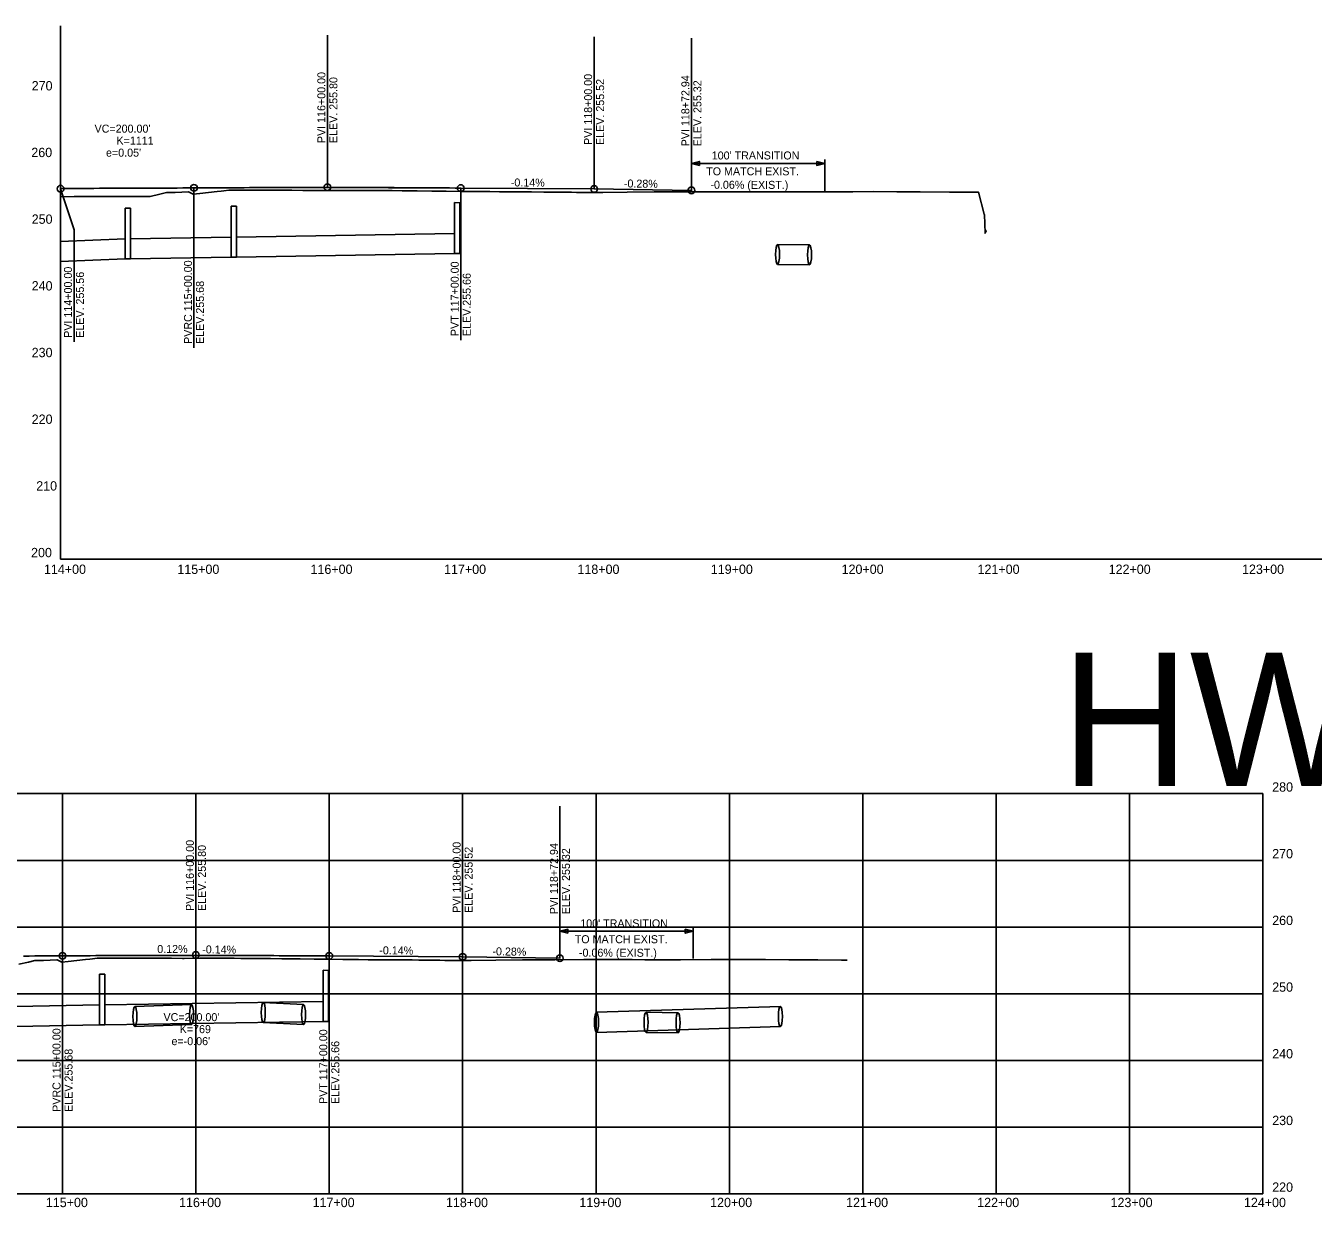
# Model space of a CAD drawing. Extents: x 1930770 to 1938778, y 596900 to 600561.
# Drawn here: x 1933865 to 1934830, y 598564 to 599450 of the extents above; entities that cross this region are included whole.
import ezdxf

# ---------------------------------------------------------------- set-up
doc = ezdxf.new("R2010")
doc.units = 0
for name, color, linetype in [('E_Tract Residual', 7, 'Continuous'), ('R_Concrete Hidden', 7, 'Continuous'), ('S_CROSS_DRAIN_ANNOT', 7, 'Continuous'), ('S_DROP_INLET_ANNOT', 7, 'Continuous'), ('S_ELECTRIC_UTILITIES_ANNOT', 7, 'Continuous'), ('S_HIST_HIGH_WATER_ANNOT', 7, 'Continuous'), ('S_SIGN_ANNOT', 7, 'Continuous'), ('S_STORM_SEWER_ANNOT', 7, 'Continuous'), ('S_UTILITY_POLE_ANNOT', 7, 'Continuous'), ('S_WATER_UTILITIES_ANNOT', 7, 'Continuous')]:
    doc.layers.add(name, color=color, linetype=linetype)

msp = doc.modelspace()

# ---------------------------------------------------------------- linework, layer by layer
at = {"layer": 'R_Concrete Hidden'}
for p, q in [((1933939.7, 599313.51), (1933943.7, 599313.66)), ((1933939.7, 599275.51), (1933939.7, 599313.51)), ((1933943.7, 599275.51), (1933943.7, 599313.66)), ((1934019.06, 599314.95), (1934023.06, 599315.06)), ((1934019.06, 599276.86), (1934019.06, 599314.95)), ((1934023.06, 599276.86), (1934023.06, 599315.06)), ((1934186.58, 599279.51), (1934186.58, 599317.88)), ((1934186.58, 599317.88), (1934190.58, 599317.6)), ((1934190.58, 599279.51), (1934190.58, 599317.6)), ((1934186.58, 599294.51), (1934023.06, 599291.86)), ((1933939.7, 599290.51), (1933891.24, 599288.55)), ((1934019.06, 599291.86), (1933943.7, 599290.51)), ((1934428.77, 599286.36), (1934452.75, 599286.06)), ((1933939.7, 599275.51), (1933891.24, 599273.55)), ((1933939.7, 599275.51), (1933943.7, 599275.51)), ((1934019.06, 599276.86), (1933943.7, 599275.51)), ((1934019.06, 599276.86), (1934023.06, 599276.86)), ((1934186.58, 599279.51), (1934023.06, 599276.86)), ((1934186.58, 599279.51), (1934190.58, 599279.51)), ((1934428.77, 599271.36), (1934452.75, 599271.06)), ((1933920.49, 598739.19), (1933924.49, 598739.3)), ((1933920.49, 598701.1), (1933920.49, 598739.19)), ((1933924.49, 598701.1), (1933924.49, 598739.3)), ((1934088.01, 598703.75), (1934088.01, 598742.13)), ((1934088.01, 598742.13), (1934092.01, 598741.85)), ((1934092.01, 598703.75), (1934092.01, 598741.85)), ((1933920.49, 598716.1), (1933845.13, 598714.75)), ((1934088.01, 598718.75), (1933924.49, 598716.1)), ((1934088.01, 598703.75), (1933924.49, 598701.1)), ((1934088.01, 598703.75), (1934092.01, 598703.75)), ((1934330.2, 598710.6), (1934354.18, 598710.3)), ((1933920.49, 598701.1), (1933845.13, 598699.75)), ((1933920.49, 598701.1), (1933924.49, 598701.1)), ((1934330.2, 598695.6), (1934354.18, 598695.3))]:
    msp.add_line(p, q, dxfattribs=at)
for centre in [(1934428.77, 599278.86), (1934452.75, 599278.56), (1934330.2, 598703.1), (1934354.18, 598702.8)]:
    msp.add_ellipse(centre, major_axis=(0, 7.5), ratio=0.2, dxfattribs=at)
at = {"layer": 'S_CROSS_DRAIN_ANNOT'}
for p, q in [((1933891.24, 599050.31), (1933891.24, 599450.31)), ((1933891.24, 599050.31), (1935391.24, 599050.31)), ((1934792.67, 598574.55), (1934792.67, 598874.55)), ((1932092.67, 598574.55), (1934792.67, 598574.55))]:
    msp.add_line(p, q, dxfattribs=at)
at = {"layer": 'S_ELECTRIC_UTILITIES_ANNOT'}
for p, q in [((1934091.24, 599359.32), (1934091.24, 599443.32)), ((1934291.24, 599357.92), (1934291.24, 599441.92)), ((1934364.18, 599356.9), (1934364.18, 599440.9)), ((1934091.24, 599329.32), (1934091.24, 599359.32)), ((1934291.24, 599327.92), (1934291.24, 599357.92)), ((1934364.18, 599326.9), (1934364.18, 599356.9)), ((1933891.24, 599328.12), (1933941.24, 599328.42)), ((1933891.24, 599328.12), (1933891.24, 599328.12)), ((1933891.24, 599328.12), (1933901.27, 599297.34)), ((1933991.24, 599328.72), (1933991.24, 599298.72)), ((1934041.24, 599329.02), (1934091.24, 599329.32)), ((1934091.24, 599329.32), (1934141.24, 599328.97)), ((1934191.24, 599328.62), (1934191.24, 599298.62)), ((1933901.27, 599297.34), (1933901.27, 599213.34)), ((1933991.24, 599298.72), (1933991.24, 599208.72)), ((1934191.24, 599298.62), (1934191.24, 599214.62)), ((1933992.67, 598783.57), (1933992.67, 598867.57)), ((1934192.67, 598782.17), (1934192.67, 598866.17)), ((1934265.61, 598781.15), (1934265.61, 598865.15)), ((1933992.67, 598753.57), (1933992.67, 598783.57)), ((1934192.67, 598752.17), (1934192.67, 598782.17)), ((1934265.61, 598751.15), (1934265.61, 598781.15)), ((1933892.67, 598752.97), (1933892.67, 598722.97)), ((1933942.67, 598753.27), (1933992.67, 598753.57)), ((1933992.67, 598753.57), (1934042.67, 598753.22)), ((1934092.67, 598752.87), (1934092.67, 598722.87)), ((1933892.67, 598722.97), (1933892.67, 598632.97)), ((1934092.67, 598722.87), (1934092.67, 598638.87))]:
    msp.add_line(p, q, dxfattribs=at)
for centre in [(1933991.24, 599328.72), (1934091.24, 599329.32), (1933891.24, 599328.12), (1934191.24, 599328.62), (1934291.24, 599327.92), (1934364.18, 599326.9), (1933892.67, 598752.97), (1933992.67, 598753.57), (1934092.67, 598752.87), (1934192.67, 598752.17), (1934265.61, 598751.15)]:
    msp.add_circle(centre, 2.5, dxfattribs=at)
at = {"layer": 'S_HIST_HIGH_WATER_ANNOT'}
for p, q in [((1934191.24, 599328.62), (1934291.24, 599327.92)), ((1934291.24, 599327.92), (1934364.18, 599326.9)), ((1934092.67, 598752.87), (1934192.67, 598752.17)), ((1934192.67, 598752.17), (1934265.61, 598751.15))]:
    msp.add_line(p, q, dxfattribs=at)
for points in [[(1933891.24, 599328.35), (1933895.41, 599328.35), (1933899.58, 599328.36), (1933903.74, 599328.37), (1933907.91, 599328.38), (1933912.08, 599328.39), (1933916.24, 599328.4), (1933920.41, 599328.41), (1933924.58, 599328.42), (1933928.74, 599328.43), (1933932.91, 599328.45), (1933937.08, 599328.46), (1933941.24, 599328.48), (1933945.41, 599328.49), (1933949.58, 599328.51), (1933953.74, 599328.53), (1933957.91, 599328.55), (1933962.08, 599328.56), (1933966.24, 599328.58), (1933970.41, 599328.61), (1933974.58, 599328.63), (1933978.74, 599328.65), (1933982.91, 599328.67), (1933987.08, 599328.7), (1933991.24, 599328.72)], [(1933991.24, 599328.72), (1933995.41, 599328.75), (1933999.58, 599328.77), (1934003.74, 599328.79), (1934007.91, 599328.81), (1934012.08, 599328.83), (1934016.24, 599328.85), (1934020.41, 599328.87), (1934024.58, 599328.88), (1934028.74, 599328.9), (1934032.91, 599328.91), (1934037.08, 599328.93), (1934041.24, 599328.94), (1934045.41, 599328.95), (1934049.58, 599328.96), (1934053.74, 599328.97), (1934057.91, 599328.98), (1934062.08, 599328.98), (1934066.24, 599328.99), (1934070.41, 599328.99), (1934074.58, 599328.99), (1934078.74, 599329), (1934082.91, 599329), (1934087.08, 599329), (1934095.41, 599328.99), (1934099.58, 599328.99), (1934103.74, 599328.98), (1934107.91, 599328.98), (1934112.08, 599328.97), (1934116.24, 599328.96), (1934120.41, 599328.95), (1934124.58, 599328.94), (1934128.74, 599328.93), (1934132.91, 599328.92), (1934137.08, 599328.9), (1934141.24, 599328.89), (1934145.41, 599328.87), (1934149.58, 599328.86), (1934153.74, 599328.84), (1934157.91, 599328.82), (1934162.08, 599328.8), (1934166.24, 599328.78), (1934170.41, 599328.75), (1934174.58, 599328.73), (1934178.74, 599328.7), (1934182.91, 599328.68), (1934187.08, 599328.65), (1934191.24, 599328.62)], [(1933863.5, 598752.81), (1933867.67, 598752.83), (1933871.83, 598752.85), (1933876, 598752.87), (1933880.17, 598752.9), (1933884.33, 598752.92), (1933888.5, 598752.94), (1933892.67, 598752.97)], [(1933892.67, 598752.97), (1933896.83, 598752.99), (1933901, 598753.01), (1933905.17, 598753.04), (1933909.33, 598753.06), (1933913.5, 598753.08), (1933917.67, 598753.1), (1933921.83, 598753.11), (1933926, 598753.13), (1933930.17, 598753.15), (1933934.33, 598753.16), (1933938.5, 598753.17), (1933942.67, 598753.19), (1933946.83, 598753.2), (1933951, 598753.21), (1933955.17, 598753.22), (1933959.33, 598753.22), (1933963.5, 598753.23), (1933967.67, 598753.23), (1933971.83, 598753.24), (1933976, 598753.24), (1933980.17, 598753.24), (1933984.33, 598753.24), (1933988.5, 598753.24), (1933996.83, 598753.24), (1934001, 598753.24), (1934005.17, 598753.23), (1934009.33, 598753.22), (1934013.5, 598753.22), (1934017.67, 598753.21), (1934021.83, 598753.2), (1934026, 598753.19), (1934030.17, 598753.18), (1934034.33, 598753.16), (1934038.5, 598753.15), (1934042.67, 598753.14), (1934046.83, 598753.12), (1934051, 598753.1), (1934055.17, 598753.08), (1934059.33, 598753.06), (1934063.5, 598753.04), (1934067.67, 598753.02), (1934071.83, 598753), (1934076, 598752.97), (1934080.17, 598752.95), (1934084.33, 598752.92), (1934088.5, 598752.9), (1934092.67, 598752.87)]]:
    msp.add_lwpolyline(points, dxfattribs=at)
at = {"layer": 'S_SIGN_ANNOT'}
for p, q in [((1934043.2, 598718), (1934073.4, 598716.4)), ((1934430.92, 598715), (1934293.03, 598710.6)), ((1933946.94, 598699.95), (1933989.4, 598701.4)), ((1934043.2, 598703), (1934073.4, 598701.4)), ((1934293.03, 598695.6), (1934430.92, 598700))]:
    msp.add_line(p, q, dxfattribs=at)
msp.add_lwpolyline([(1933946.94, 598714.95), (1933989.4, 598716.4)], dxfattribs=at)
for centre in [(1933946.94, 598707.45), (1933989.4, 598708.9), (1934043.2, 598710.5), (1934073.4, 598708.9), (1934430.92, 598707.5), (1934293.03, 598703.1)]:
    msp.add_ellipse(centre, major_axis=(0, 7.5), ratio=0.2, dxfattribs=at)
at = {"layer": 'S_STORM_SEWER_ANNOT'}
for p, q in [((1934364.18, 599326.62), (1934364.18, 599350.09)), ((1934464.18, 599347.09), (1934364.18, 599347.09)), ((1934464.18, 599326.62), (1934464.18, 599350.09)), ((1934265.61, 598750.86), (1934265.61, 598774.33)), ((1934365.61, 598771.33), (1934265.61, 598771.33)), ((1934365.61, 598750.86), (1934365.61, 598774.33))]:
    msp.add_line(p, q, dxfattribs=at)
for points in [[(1934370.18, 599345.59), (1934364.18, 599347.09), (1934370.18, 599348.59)], [(1934458.18, 599348.59), (1934464.18, 599347.09), (1934458.18, 599345.59)], [(1934271.61, 598769.83), (1934265.61, 598771.33), (1934271.61, 598772.83)], [(1934359.61, 598772.83), (1934365.61, 598771.33), (1934359.61, 598769.83)]]:
    msp.add_lwpolyline(points, close=True, dxfattribs=at)
at = {"layer": 'S_UTILITY_POLE_ANNOT'}
for p, q in [((1932092.67, 598874.55), (1934792.67, 598874.55)), ((1932092.67, 598874.55), (1934792.67, 598874.55)), ((1933892.67, 598574.55), (1933892.67, 598874.55)), ((1933992.67, 598574.55), (1933992.67, 598874.55)), ((1934092.67, 598574.55), (1934092.67, 598874.55)), ((1934192.67, 598574.55), (1934192.67, 598874.55)), ((1934292.67, 598574.55), (1934292.67, 598874.55)), ((1934392.67, 598574.55), (1934392.67, 598874.55)), ((1934492.67, 598574.55), (1934492.67, 598874.55)), ((1934592.67, 598574.55), (1934592.67, 598874.55)), ((1934692.67, 598574.55), (1934692.67, 598874.55)), ((1932092.67, 598824.55), (1934792.67, 598824.55)), ((1932092.67, 598774.55), (1934792.67, 598774.55)), ((1932092.67, 598724.55), (1934792.67, 598724.55)), ((1932092.67, 598674.55), (1934792.67, 598674.55)), ((1932092.67, 598624.55), (1934792.67, 598624.55))]:
    msp.add_line(p, q, dxfattribs=at)
at = {"layer": 'S_WATER_UTILITIES_ANNOT'}
for points in [[(1933891.24, 599322.18), (1933893.51, 599322.13), (1933901.45, 599322.17), (1933912.79, 599322.23), (1933914.71, 599322.18), (1933922.87, 599322.23), (1933935.01, 599322.31), (1933935.93, 599322.3), (1933944.3, 599322.33), (1933956.37, 599322.37), (1933958.44, 599322.36), (1933965.73, 599324.04), (1933970.57, 599325.16), (1933977.03, 599325.3), (1933987.01, 599325.8), (1933987.15, 599325.73), (1933990.72, 599323.99), (1933995.51, 599324.51), (1934008.58, 599325.98), (1934011.69, 599326.34), (1934013.65, 599326.56), (1934017.3, 599326.92), (1934030, 599327.02), (1934030.05, 599327.02), (1934035.5, 599327.01), (1934047.19, 599327.03), (1934051.43, 599327.01), (1934058.99, 599326.96), (1934064.58, 599326.96), (1934072.86, 599326.9), (1934081.22, 599326.84), (1934082.17, 599326.83), (1934082.34, 599326.82), (1934094.28, 599326.86), (1934101.06, 599326.88), (1934103.57, 599326.86), (1934115.71, 599326.88), (1934119.88, 599326.88), (1934124.83, 599326.83), (1934137.14, 599326.73), (1934139.91, 599326.71), (1934147.23, 599326.6), (1934155.79, 599326.48), (1934158.56, 599326.45), (1934169.54, 599326.34), (1934179.99, 599326.27), (1934180.29, 599326.26), (1934191.35, 599326.12), (1934201.42, 599326.05), (1934204.13, 599326.03), (1934213.17, 599325.91), (1934220.36, 599325.83), (1934222.84, 599325.82), (1934233.32, 599325.77), (1934239.27, 599325.7), (1934244.27, 599325.68), (1934253.46, 599325.63), (1934258.31, 599325.51), (1934265.7, 599325.47), (1934274.17, 599325.41), (1934277.94, 599325.33), (1934287.12, 599325.27), (1934294.88, 599325.23), (1934297.72, 599325.2), (1934316.15, 599325.43), (1934336.22, 599325.68), (1934337.39, 599325.67), (1934359.14, 599325.78), (1934359.8, 599325.77), (1934360.44, 599325.76), (1934382.22, 599325.9), (1934382.34, 599325.9), (1934400.29, 599325.87), (1934400.36, 599325.87), (1934418.36, 599325.85), (1934418.39, 599325.85), (1934427.74, 599325.83), (1934436.41, 599325.82), (1934436.43, 599325.82), (1934454.43, 599325.78), (1934454.51, 599325.78), (1934477.54, 599325.87), (1934477.56, 599325.87), (1934477.58, 599325.87), (1934485.17, 599325.89), (1934500.62, 599325.94), (1934500.65, 599325.94), (1934518.18, 599325.87), (1934518.23, 599325.87), (1934535.74, 599325.8), (1934535.82, 599325.8), (1934557.6, 599325.61), (1934575.3, 599325.46), (1934579.45, 599325.42), (1934579.46, 599325.42), (1934579.46, 599325.42), (1934583.63, 599308.99), (1934583.97, 599308.78), (1934584.33, 599294.73), (1934584.59, 599296.85), (1934585.04, 599297.01), (1934585.3, 599295.49)], [(1933859.87, 598746.61), (1933867.15, 598748.28), (1933872, 598749.4), (1933878.46, 598749.55), (1933888.44, 598750.04), (1933888.58, 598749.97), (1933892.14, 598748.23), (1933896.93, 598748.76), (1933910, 598750.23), (1933913.12, 598750.58), (1933915.08, 598750.81), (1933918.72, 598751.16), (1933931.43, 598751.27), (1933931.47, 598751.27), (1933936.92, 598751.26), (1933948.61, 598751.27), (1933952.86, 598751.25), (1933960.41, 598751.21), (1933966, 598751.21), (1933974.28, 598751.15), (1933982.64, 598751.08), (1933983.6, 598751.07), (1933983.76, 598751.07), (1933995.71, 598751.11), (1934002.48, 598751.13), (1934004.99, 598751.1), (1934017.13, 598751.12), (1934021.3, 598751.13), (1934026.25, 598751.07), (1934038.56, 598750.98), (1934041.34, 598750.96), (1934048.66, 598750.85), (1934057.21, 598750.72), (1934059.99, 598750.7), (1934070.96, 598750.59), (1934081.41, 598750.51), (1934081.71, 598750.51), (1934092.77, 598750.37), (1934102.84, 598750.29), (1934105.55, 598750.27), (1934114.6, 598750.16), (1934121.79, 598750.08), (1934124.27, 598750.07), (1934134.74, 598750.01), (1934140.7, 598749.95), (1934145.69, 598749.92), (1934154.88, 598749.88), (1934159.73, 598749.76), (1934167.12, 598749.71), (1934175.59, 598749.66), (1934179.37, 598749.57), (1934188.55, 598749.52), (1934196.31, 598749.48), (1934199.14, 598749.44), (1934217.58, 598749.67), (1934237.65, 598749.92), (1934238.81, 598749.91), (1934260.56, 598750.03), (1934261.23, 598750.02), (1934261.86, 598750.01), (1934283.65, 598750.15), (1934283.76, 598750.15), (1934301.72, 598750.12), (1934301.79, 598750.12), (1934319.79, 598750.09), (1934319.81, 598750.09), (1934329.16, 598750.08), (1934337.83, 598750.06), (1934337.86, 598750.06), (1934355.85, 598750.03), (1934355.93, 598750.03), (1934378.96, 598750.11), (1934378.98, 598750.11), (1934379.01, 598750.11), (1934386.6, 598750.14), (1934402.04, 598750.19), (1934402.08, 598750.19), (1934419.6, 598750.12), (1934419.65, 598750.12), (1934437.16, 598750.04), (1934437.25, 598750.04), (1934459.02, 598749.86), (1934476.73, 598749.71), (1934480.87, 598749.67)]]:
    msp.add_lwpolyline(points, dxfattribs=at)

# ---------------------------------------------------------------- texts
at = {"layer": 'E_Tract Residual'}
for s, rotation, p in [('0.12%', 0.34377, (1933963.72, 598755.02)), ('-0.14%', 359.59894, (1933997.39, 598754.79))]:
    msp.add_text(s, height=6, rotation=rotation, dxfattribs=at).set_placement(p)
at = {"layer": 'S_DROP_INLET_ANNOT'}
for s, p in [('270', (1933869.55, 599401.81)), ('260', (1933869.27, 599351.81)), ('250', (1933869.55, 599301.81)), ('240', (1933869.55, 599251.81)), ('230', (1933869.55, 599201.81)), ('220', (1933869.55, 599151.81)), ('210', (1933872.95, 599101.81)), ('200', (1933869.08, 599051.81)), ('114+00', (1933878.75, 599039.31)), ('115+00', (1933978.75, 599039.31)), ('116+00', (1934078.61, 599039.31)), ('117+00', (1934178.75, 599039.31)), ('118+00', (1934278.75, 599039.31)), ('119+00', (1934378.75, 599039.31)), ('120+00', (1934476.81, 599039.31)), ('121+00', (1934578.75, 599039.31)), ('122+00', (1934677.05, 599039.31)), ('123+00', (1934777.05, 599039.31)), ('280', (1934799.67, 598876.05)), ('280', (1934799.67, 598876.05)), ('270', (1934799.67, 598826.05)), ('260', (1934799.67, 598776.05)), ('250', (1934799.67, 598726.05)), ('240', (1934799.67, 598676.05)), ('230', (1934799.67, 598626.05)), ('220', (1934799.67, 598576.05)), ('115+00', (1933880.17, 598564.55)), ('116+00', (1933980.03, 598564.55)), ('117+00', (1934080.17, 598564.55)), ('118+00', (1934180.17, 598564.55)), ('119+00', (1934280.17, 598564.55)), ('120+00', (1934378.23, 598564.55)), ('121+00', (1934480.17, 598564.55)), ('122+00', (1934578.47, 598564.55)), ('123+00', (1934678.47, 598564.55)), ('124+00', (1934778.47, 598564.55))]:
    msp.add_text(s, height=7, dxfattribs=at).set_placement(p)
at = {"layer": 'S_ELECTRIC_UTILITIES_ANNOT'}
for s, rotation, p in [('PVI 116+00.00', 90, (1934089.74, 599362.32)), ('ELEV. 255.80', 90, (1934098.74, 599362.32)), ('PVI 118+00.00', 90, (1934289.74, 599360.92)), ('ELEV. 255.52', 90, (1934298.74, 599360.92)), ('PVI 118+72.94', 90, (1934362.68, 599359.9)), ('ELEV. 255.32', 90, (1934371.68, 599359.9)), ('-0.14%', 359.59894, (1934228.76, 599329.86)), ('-0.28%', 359.19791, (1934313.54, 599329.11)), ('-0.06% (EXIST.)', 359.87313, (1934378.46, 599328.1)), ('PVRC 115+00.00', 90, (1933989.74, 599211.72)), ('PVT 117+00.00', 90, (1934189.74, 599217.62)), ('PVI 114+00.00', 90, (1933899.77, 599216.34)), ('ELEV. 255.56', 90, (1933908.77, 599216.34)), ('ELEV.255.66', 90, (1934198.74, 599217.62)), ('ELEV.255.68', 90, (1933998.74, 599211.72)), ('PVI 116+00.00', 90, (1933991.17, 598786.57)), ('ELEV. 255.80', 90, (1934000.17, 598786.57)), ('PVI 118+00.00', 90, (1934191.17, 598785.17)), ('ELEV. 255.52', 90, (1934200.17, 598785.17)), ('PVI 118+72.94', 90, (1934264.11, 598784.15)), ('ELEV. 255.32', 90, (1934273.11, 598784.15)), ('-0.14%', 359.59894, (1934130.18, 598754.1)), ('-0.28%', 359.19791, (1934214.96, 598753.36)), ('-0.06% (EXIST.)', 359.87313, (1934279.88, 598752.35)), ('PVRC 115+00.00', 90, (1933891.17, 598635.97)), ('PVT 117+00.00', 90, (1934091.17, 598641.87)), ('ELEV.255.66', 90, (1934100.17, 598641.87)), ('ELEV.255.68', 90, (1933900.17, 598635.97))]:
    msp.add_text(s, height=6, rotation=rotation, dxfattribs=at).set_placement(p)
for s, p in [("VC=200.00'", (1933916.68, 599370.16)), ('K=1111', (1933933.12, 599361.16)), ("e=0.05'", (1933925.28, 599352.16)), ("VC=200.00'", (1933968.35, 598703.99)), ('K=769', (1933980.52, 598694.99)), ("e=-0.06'", (1933974.35, 598685.99))]:
    msp.add_text(s, height=6, dxfattribs=at).set_placement(p)
at = {"layer": 'S_STORM_SEWER_ANNOT'}
for s, p in [("100' TRANSITION", (1934379.44, 599350.06)), ('TO MATCH EXIST.', (1934375.3, 599338.17)), ("100' TRANSITION", (1934280.87, 598774.31)), ('TO MATCH EXIST.', (1934276.73, 598762.41))]:
    msp.add_text(s, height=6, rotation=0.00482, dxfattribs=at).set_placement(p)
for s, height, p in [('-', 0.0001, (1933891.24, 599050.31)), ('HWY 61', 100, (1934641.24, 598880.31))]:
    msp.add_text(s, height=height, dxfattribs=at).set_placement(p)

doc.saveas('drawing.dxf')
